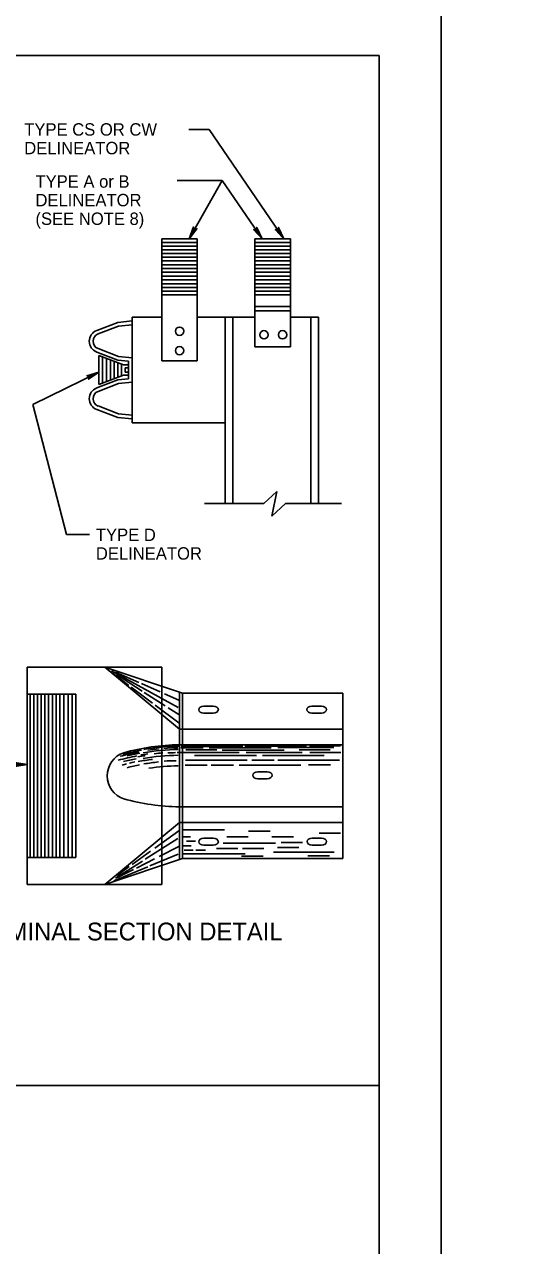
# Model space of a CAD drawing. Extents: x 640253 to 641999, y 298458 to 299646.
# Drawn here: x 640993.6 to 641116.9, y 298748.9 to 299044.1 of the extents above; entities that cross this region are included whole.
import ezdxf

# ---------------------------------------------------------------- set-up
doc = ezdxf.new("R2010")
doc.units = 0
for name, color, linetype in [('1', 7, 'Continuous'), ('2', 7, 'Continuous'), ('PLT-BNDY', 7, 'Continuous')]:
    doc.layers.add(name, color=color, linetype=linetype)

msp = doc.modelspace()

# ---------------------------------------------------------------- linework, layer by layer
at = {"layer": '1'}
for p, q in [((640293.31, 299036.63), (641079.31, 299036.63)), ((641079.31, 298472.63), (641079.31, 299036.63)), ((640994.25, 298888.75), (640994.25, 298836.25)), ((641026.75, 298888.75), (640994.25, 298888.75)), ((641031.75, 298882.5), (641013, 298888.75)), ((641031, 298873.75), (641013, 298888.75)), ((641014.58, 298887.88), (641030.72, 298879.02)), ((641014.77, 298887.42), (641018.82, 298884.36)), ((641015.6, 298887.58), (641021.2, 298885.08)), ((641015.79, 298886.96), (641022, 298882.97)), ((641026.75, 298888.75), (641026.75, 298884.16)), ((641019.37, 298883.95), (641024.48, 298880.09)), ((641021.85, 298884.79), (641026.4, 298882.76)), ((641026.75, 298883.98), (641026.75, 298840.92)), ((641006.01, 298882.25), (640994.25, 298882.25)), ((641006.01, 298882.25), (641006.01, 298842.75)), ((641022.53, 298882.63), (641027.57, 298879.41)), ((641027.37, 298882.32), (641030.88, 298880.76)), ((641031, 298842.25), (641031, 298882.75)), ((641070.5, 298882.5), (641031.75, 298882.5)), ((641031.75, 298842.5), (641031.75, 298882.5)), ((641070.5, 298842.5), (641070.5, 298882.5)), ((641025.16, 298879.58), (641030.86, 298875.29)), ((641028.3, 298878.93), (641030.85, 298877.3)), ((641039.17, 298877.65), (641036.93, 298877.65)), ((641036.94, 298879.34), (641039.18, 298879.33)), ((641063.06, 298879.34), (641065.31, 298879.33)), ((641065.3, 298877.65), (641063.06, 298877.65)), ((641070.5, 298873.75), (641031, 298873.75)), ((641070.5, 298870), (641031, 298870)), ((641036.74, 298869.24), (641031.39, 298869.24)), ((641046.34, 298869.59), (641031.41, 298869.59)), ((641040.08, 298868.78), (641032.6, 298868.78)), ((641053.17, 298869.29), (641038.23, 298869.29)), ((641056.3, 298868.73), (641041.36, 298868.73)), ((641061.76, 298869.64), (641046.82, 298869.64)), ((641068.33, 298869.34), (641054.84, 298869.34)), ((641067.42, 298868.78), (641059.94, 298868.78)), ((641069.95, 298869.74), (641062.47, 298869.74)), ((641045.44, 298868.13), (641030.5, 298868.13)), ((641047.41, 298866.26), (641032.47, 298866.26)), ((641049.63, 298867.42), (641034.69, 298867.42)), ((641060.65, 298868.13), (641047.15, 298868.13)), ((641053.88, 298866.31), (641048.52, 298866.31)), ((641066, 298867.37), (641051.07, 298867.37)), ((641069.74, 298866.31), (641054.81, 298866.31)), ((641070, 298868.13), (641062.52, 298868.13)), ((641037.75, 298865.09), (641032.4, 298865.09)), ((641044.07, 298865.04), (641038.71, 298865.04)), ((641060.39, 298865.04), (641045.46, 298865.04)), ((641049.98, 298863.48), (641052.22, 298863.48)), ((641067.57, 298865.14), (641062.21, 298865.14)), ((641052.21, 298861.79), (641049.97, 298861.8)), ((641070.5, 298855), (641031, 298855)), ((641031, 298851.25), (641013, 298836.25)), ((641070.5, 298851.25), (641031, 298851.25)), ((641025.08, 298845.03), (641030.87, 298849.21)), ((641031.87, 298849.46), (641041.94, 298849.46)), ((641047.73, 298849.13), (641052.91, 298849.13)), ((641064.81, 298848.63), (641069.98, 298848.63)), ((641022.75, 298842.32), (641030.62, 298847.36)), ((641026.12, 298842.98), (641030.87, 298845.37)), ((641031.87, 298845.57), (641033.89, 298845.57)), ((641031.98, 298847.72), (641033.73, 298847.72)), ((641032.69, 298846.68), (641034.9, 298846.68)), ((641039.17, 298845.72), (641036.93, 298845.73)), ((641036.94, 298847.41), (641039.18, 298847.41)), ((641041.61, 298846.25), (641054.22, 298846.25)), ((641042.47, 298847.72), (641047.65, 298847.72)), ((641053.39, 298847.72), (641058.56, 298847.72)), ((641054.7, 298845.19), (641059.88, 298845.19)), ((641055.61, 298846.4), (641060.79, 298846.4)), ((641063.11, 298847.45), (641065.36, 298847.45)), ((641065.35, 298845.76), (641063.11, 298845.76)), ((641006.01, 298842.75), (640994.25, 298842.75)), ((641031.75, 298842.5), (641013, 298836.25)), ((641019.56, 298841.03), (641024.04, 298844.27)), ((641020.61, 298840.19), (641024.99, 298842.39)), ((641023.87, 298840.74), (641030.75, 298843.59)), ((641070.5, 298842.5), (641031.75, 298842.5)), ((641031.85, 298843.63), (641046.89, 298843.63)), ((641032.13, 298844.56), (641034.34, 298844.56)), ((641035, 298844.56), (641037.31, 298844.56)), ((641039.95, 298844.89), (641045.13, 298844.89)), ((641046.05, 298843.04), (641051.23, 298843.04)), ((641046.25, 298844.91), (641051.43, 298844.91)), ((641053.74, 298844.03), (641068.42, 298844.03)), ((641062.08, 298843.17), (641067.26, 298843.17)), ((641015.14, 298837.13), (641023.34, 298840.52)), ((641015.59, 298837.75), (641022.06, 298841.88)), ((641015.94, 298838.41), (641018.89, 298840.55)), ((641016.01, 298837.88), (641019.88, 298839.83)), ((641026.75, 298840.85), (641026.75, 298836.25)), ((641026.75, 298836.25), (640994.25, 298836.25)), ((640293.31, 298787.67), (641079.31, 298787.67))]:
    msp.add_line(p, q, dxfattribs=at)
for centre, radius, start, end in [((641031.51, 298816.8), 52.79, 100.5386, 105.5487), ((641031.71, 298817.21), 52.79, 90.7697, 105.5487), ((641031.43, 298816.07), 52.79, 90.7697, 100.0032), ((641031.61, 298816.9), 52.79, 90.7697, 100.0032), ((641031.36, 298816.5), 52.79, 95.7095, 98.7189), ((641031.36, 298816.5), 52.79, 90.7697, 94.465), ((641019.44, 298862.5), 5.88, 108.6699, 251.835), ((641030.35, 298815.39), 52.79, 100.5386, 105.5487), ((641030.85, 298816.35), 52.79, 100.5386, 105.5487), ((641030.22, 298814.73), 52.79, 100.5386, 103.989), ((641031.11, 298816.07), 52.79, 100.5386, 103.989), ((641031.33, 298814.25), 52.79, 102.1044, 103.5962), ((641030.17, 298815.09), 52.79, 98.1369, 100.0032), ((641030.2, 298813.97), 52.79, 96.1764, 100.0032), ((641030.88, 298815.54), 52.79, 98.1369, 100.0032), ((641031.41, 298814.68), 52.79, 90.7697, 100.0032), ((641031.61, 298813.37), 52.79, 96.1764, 100.0032), ((641031.13, 298815.41), 52.79, 94.5197, 96.728), ((641030.93, 298813.37), 52.79, 90.7697, 93.8884), ((641030.75, 298815.31), 52.79, 90.7697, 92.7909), ((641031.33, 298814.23), 52.79, 104.3483, 105.5487), ((641031.06, 298813.22), 52.79, 100.5386, 103.9089), ((641031.46, 298812.13), 52.79, 90.7697, 98.5017), ((641031.71, 298907.78), 52.79, 254.4513, 269.2303)]:
    msp.add_arc(centre, radius, start, end, dxfattribs=at)
for centre, start_param, end_param in [((641036.94, 298878.49), 1.590592, 4.707341), ((641039.18, 298878.49), 4.732181, 7.83878), ((641063.06, 298878.5), 1.590592, 4.707341), ((641065.3, 298878.49), 4.732181, 7.83878), ((641049.97, 298862.64), 1.590592, 4.707341), ((641052.22, 298862.64), 4.732181, 7.83878), ((641036.94, 298846.57), 1.590592, 4.707341), ((641039.18, 298846.57), 4.732181, 7.83878), ((641063.11, 298846.61), 1.590592, 4.707341), ((641065.35, 298846.6), 4.732181, 7.83878)]:
    msp.add_ellipse(centre, major_axis=(1.25, 0), ratio=0.675, start_param=start_param, end_param=end_param, dxfattribs=at)
at = {"layer": '2'}
for p, q in [((641033.28, 299018.74), (641038.18, 299018.74)), ((641038.18, 299018.74), (641056.27, 298992.32)), ((641030.49, 299006.38), (641041.37, 299006.38)), ((641041.37, 299006.38), (641033.38, 298992.32)), ((641041.37, 299006.38), (641051.01, 298992.32)), ((641026.75, 298992.32), (641026.75, 298962.78)), ((641035.34, 298992.32), (641026.75, 298992.32)), ((641035.34, 298991.44), (641026.75, 298991.44)), ((641035.34, 298990.54), (641026.75, 298990.54)), ((641035.34, 298992.18), (641035.2, 298992.32)), ((641035.34, 298992.32), (641035.34, 298962.78)), ((641057.84, 298992.32), (641049.25, 298992.32)), ((641049.25, 298992.32), (641049.25, 298966.23)), ((641057.84, 298991.44), (641049.25, 298991.44)), ((641057.84, 298990.54), (641049.25, 298990.54)), ((641057.84, 298991.92), (641057.7, 298992.06)), ((641057.84, 298992.32), (641057.84, 298966.23)), ((641035.34, 298989.64), (641026.75, 298989.64)), ((641035.34, 298988.74), (641026.75, 298988.74)), ((641035.34, 298987.84), (641026.75, 298987.84)), ((641035.34, 298986.94), (641026.75, 298986.94)), ((641057.84, 298989.64), (641049.25, 298989.64)), ((641057.84, 298988.74), (641049.25, 298988.74)), ((641057.84, 298987.84), (641049.25, 298987.84)), ((641057.84, 298986.94), (641049.25, 298986.94)), ((641035.34, 298986.04), (641026.75, 298986.04)), ((641035.34, 298985.14), (641026.75, 298985.14)), ((641035.34, 298984.24), (641026.75, 298984.24)), ((641057.84, 298986.04), (641049.25, 298986.04)), ((641057.84, 298985.14), (641049.25, 298985.14)), ((641057.84, 298984.24), (641049.25, 298984.24)), ((641035.34, 298983.26), (641026.75, 298983.26)), ((641035.34, 298982.36), (641026.75, 298982.36)), ((641035.34, 298981.46), (641026.75, 298981.46)), ((641057.84, 298983.26), (641049.25, 298983.26)), ((641057.84, 298982.36), (641049.25, 298982.36)), ((641057.84, 298981.46), (641049.25, 298981.46)), ((641035.34, 298980.56), (641026.75, 298980.56)), ((641035.34, 298979.66), (641026.75, 298979.66)), ((641035.34, 298978.76), (641026.75, 298978.76)), ((641057.84, 298980.56), (641049.25, 298980.56)), ((641057.84, 298979.66), (641049.25, 298979.66)), ((641057.84, 298978.76), (641049.25, 298978.76)), ((641057.84, 298975.96), (641049.25, 298975.96)), ((641057.84, 298974.89), (641049.25, 298974.89)), ((641011.02, 298970.14), (641016.09, 298972.1)), ((641019.6, 298972.45), (641016.09, 298972.1)), ((641019.6, 298973.35), (641019.6, 298947.85)), ((641026.75, 298973.35), (641019.6, 298973.35)), ((641042.1, 298973.35), (641035.34, 298973.35)), ((641042.1, 298973.35), (641042.1, 298928.35)), ((641049.25, 298973.35), (641042.1, 298973.35)), ((641043.9, 298973.35), (641043.9, 298928.35)), ((641064.6, 298973.35), (641057.84, 298973.35)), ((641062.8, 298973.35), (641062.8, 298928.35)), ((641064.6, 298973.35), (641064.6, 298928.35)), ((641011.34, 298969.3), (641016.3, 298971.22)), ((641019.6, 298971.54), (641016.3, 298971.22)), ((641057.84, 298966.23), (641049.25, 298966.23)), ((641011.02, 298964.94), (641016.09, 298962.98)), ((641011.34, 298965.78), (641016.3, 298963.86)), ((641011.55, 298964.12), (641017.49, 298961.83)), ((641011.55, 298964.12), (641011.55, 298957.07)), ((641012.43, 298957.41), (641012.43, 298963.78)), ((641013.37, 298957.78), (641013.37, 298963.42)), ((641019.6, 298963.54), (641016.3, 298963.86)), ((641014.32, 298958.14), (641014.32, 298963.05)), ((641015.22, 298958.49), (641015.22, 298962.7)), ((641018.7, 298962.73), (641016.09, 298962.98)), ((641016.12, 298958.84), (641016.12, 298962.36)), ((641017.02, 298959.18), (641017.02, 298962.01)), ((641018.7, 298961.83), (641017.49, 298961.83)), ((641017.93, 298961.15), (641017.93, 298960.04)), ((641018.7, 298961.15), (641017.93, 298961.15)), ((641018.7, 298962.73), (641018.7, 298958.47)), ((641018.7, 298961.83), (641018.7, 298961.15)), ((641035.34, 298962.78), (641026.75, 298962.78)), ((641011.55, 298960.09), (640995.61, 298952.27)), ((641011.02, 298956.25), (641016.09, 298958.21)), ((641011.34, 298955.41), (641016.3, 298957.33)), ((641011.55, 298957.07), (641017.49, 298959.36)), ((641018.7, 298958.47), (641016.09, 298958.21)), ((641019.6, 298957.65), (641016.3, 298957.33)), ((641018.7, 298959.36), (641017.49, 298959.36)), ((641018.7, 298960.04), (641017.93, 298960.04)), ((641018.7, 298960.04), (641018.7, 298959.36)), ((640995.61, 298952.27), (641003.72, 298920.79)), ((641011.34, 298951.89), (641016.3, 298949.97)), ((641011.02, 298951.05), (641016.09, 298949.09)), ((641019.6, 298948.75), (641016.09, 298949.09)), ((641019.6, 298949.65), (641016.3, 298949.97)), ((641042.1, 298947.85), (641019.6, 298947.85)), ((641051.38, 298928.35), (641054.56, 298931.19)), ((641054.56, 298931.19), (641053.32, 298925.29)), ((641051.38, 298928.35), (641037.06, 298928.35)), ((641053.32, 298925.29), (641056.66, 298928.35)), ((641070.15, 298928.35), (641056.66, 298928.35)), ((641003.72, 298920.79), (641009.3, 298920.79)), ((640994.9, 298842.75), (640994.9, 298882.25)), ((640995.8, 298842.75), (640995.8, 298882.25)), ((640996.7, 298842.75), (640996.7, 298882.25)), ((640997.6, 298842.75), (640997.6, 298882.25)), ((640998.5, 298842.75), (640998.5, 298882.25)), ((640999.4, 298842.75), (640999.4, 298882.25)), ((641000.3, 298842.75), (641000.3, 298882.25)), ((641001.2, 298842.75), (641001.2, 298882.25)), ((641002.1, 298842.75), (641002.1, 298882.25)), ((641003.1, 298842.75), (641003.1, 298882.25)), ((641004.1, 298842.75), (641004.1, 298882.25)), ((641005.1, 298842.75), (641005.1, 298882.25)), ((640973.4, 298865.2), (640994.25, 298865.2))]:
    msp.add_line(p, q, dxfattribs=at)
for points in [[(641035.05, 298994.66), (641034.82, 298994.66), (641033.38, 298992.32), (641035.05, 298994.66), (641035.23, 298994.73), (641033.38, 298992.32), (641034.57, 298994.8), (641034.43, 298994.98), (641033.38, 298992.32), (641034.39, 298995.18), (641034.43, 298994.98)], [(641049.69, 298994.88), (641049.58, 298994.67), (641051.01, 298992.32), (641049.69, 298994.88), (641049.71, 298995.07), (641051.01, 298992.32), (641049.34, 298994.51), (641049.12, 298994.47), (641051.01, 298992.32), (641048.92, 298994.52), (641049.12, 298994.47)], [(641054.95, 298994.88), (641054.84, 298994.67), (641056.27, 298992.32), (641054.95, 298994.88), (641054.97, 298995.07), (641056.27, 298992.32), (641054.61, 298994.51), (641054.38, 298994.47), (641056.27, 298992.32), (641054.18, 298994.52), (641054.38, 298994.47)], [(641008.83, 298959.15), (641009.02, 298959.01), (641011.55, 298960.09), (641008.83, 298959.15), (641008.64, 298959.2), (641011.55, 298960.09), (641009.15, 298958.75), (641009.15, 298958.53), (641011.55, 298960.09), (641009.07, 298958.34), (641009.15, 298958.53)], [(640991.4, 298865.56), (640991.5, 298865.35), (640994.25, 298865.2), (640991.4, 298865.56), (640991.25, 298865.69), (640994.25, 298865.2), (640991.51, 298865.07), (640991.41, 298864.86), (640994.25, 298865.2), (640991.25, 298864.73), (640991.41, 298864.86)]]:
    msp.add_lwpolyline(points, dxfattribs=at)
for centre in [(641031.05, 298969.97), (641051.45, 298969.1), (641055.94, 298969.1), (641031.05, 298965.27)]:
    msp.add_circle(centre, 1, dxfattribs=at)
for centre, radius in [((641012.02, 298967.54), 2.79), ((641012.02, 298967.54), 1.89), ((641012.02, 298953.65), 2.79), ((641012.02, 298953.65), 1.89)]:
    msp.add_arc(centre, radius, 111.1095, 248.8905, dxfattribs=at)
at = {"layer": 'PLT-BNDY'}
for points in [[(640253.31, 299051.63), (641094.31, 299051.63), (641094.31, 298457.63), (640253.31, 298457.63)], [(641094.31, 299051.63), (641935.31, 299051.63), (641935.31, 298457.63), (641094.31, 298457.63)]]:
    msp.add_lwpolyline(points, close=True, dxfattribs=at)

# ---------------------------------------------------------------- texts
at = {"layer": '2'}
for s, height, p in [('TYPE CS OR CW', 3, (640993.51, 299017.24)), ('DELINEATOR', 3, (640993.51, 299012.74)), ('TYPE A or B', 3, (640996.22, 299004.66)), ('DELINEATOR', 3, (640996.22, 299000.16)), ('(SEE NOTE 8)', 3, (640996.22, 298995.66)), ('TYPE D', 3, (641010.82, 298919.25)), ('DELINEATOR', 3, (641010.82, 298914.75)), ('TERMINAL SECTION DETAIL', 4.3, (640977.99, 298822.71))]:
    msp.add_text(s, height=height, dxfattribs=at).set_placement(p)

doc.saveas('drawing.dxf')
